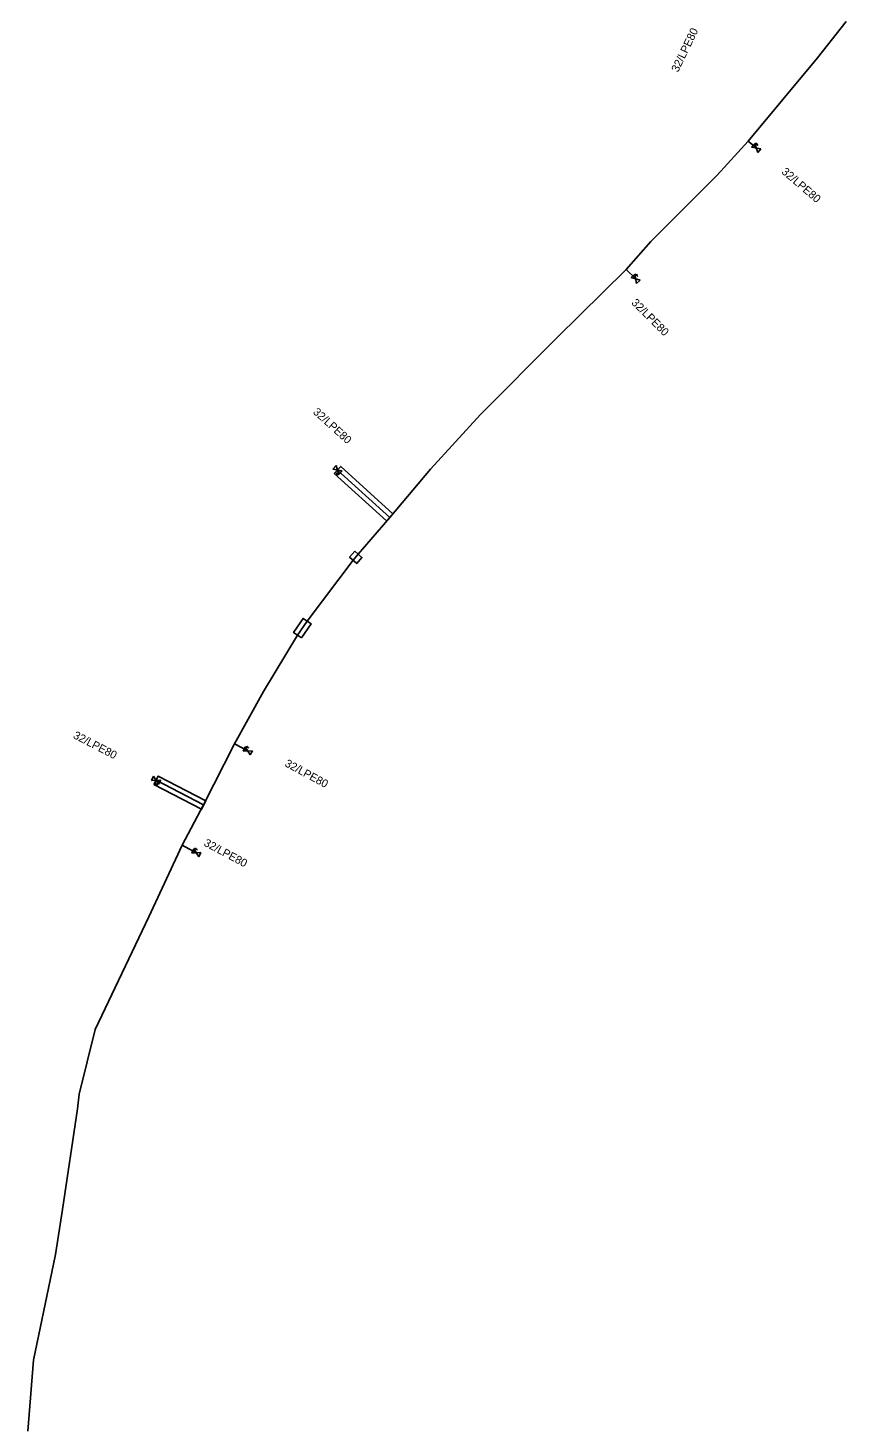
# Model space of a CAD drawing. Extents: x -787723 to -786204, y -1153846 to -1152384.
# Drawn here: x -787335.4 to -787233.1, y -1152772.9 to -1152598 of the extents above; entities that cross this region are included whole.
import ezdxf

# ---------------------------------------------------------------- set-up
doc = ezdxf.new("R2010")
doc.units = 0
for name, color, linetype in [('Vrstva 1', 7, 'Continuous'), ('Vrstva 21', 7, 'Continuous'), ('Vrstva 29', 7, 'Continuous'), ('Vrstva 31', 7, 'Continuous'), ('Vrstva 32', 7, 'Continuous')]:
    doc.layers.add(name, color=color, linetype=linetype)

# ---------------------------------------------------------------- blocks, each defined once
blk = doc.blocks.new('DEC063-SN')
at = {"layer": 'Vrstva 1'}
for p, q in [((-0.5, -0.3), (0.5, 0.3)), ((0.5, -0.3), (-0.5, 0.3)), ((-0.5, 0.3), (-0.5, -0.3)), ((0.5, 0.3), (0.5, -0.3)), ((0.126, -0.318), (0.126, -0.458)), ((0.126, -0.384), (0.206, -0.384)), ((0.206, -0.458), (0.206, -0.318)), ((0.366, -0.458), (0.366, -0.318))]:
    blk.add_line(p, q, dxfattribs=at)
for points in [[(0.246, -0.318), (0.246, -0.418), (0.252, -0.438), (0.264, -0.451), (0.281, -0.458), (0.292, -0.458), (0.309, -0.451), (0.321, -0.438), (0.326, -0.418), (0.326, -0.318)], [(0.366, -0.318), (0.418, -0.318), (0.435, -0.325), (0.441, -0.331), (0.446, -0.344), (0.446, -0.364), (0.441, -0.378), (0.435, -0.384), (0.418, -0.391), (0.366, -0.391)]]:
    blk.add_lwpolyline(points, dxfattribs=at)

msp = doc.modelspace()

# ---------------------------------------------------------------- linework, layer by layer
at = {"layer": 'Vrstva 21'}
msp.add_lwpolyline([(-787233.13, -1152597.19), (-787236.68, -1152601.75), (-787245.35, -1152612.14), (-787249.23, -1152616.39), (-787257.51, -1152624.7), (-787260.59, -1152628.17), (-787269.27, -1152636.7), (-787278.8, -1152646.28), (-787285.05, -1152653.13), (-787290.15, -1152659.16), (-787294.09, -1152663.76), (-787294.73, -1152664.5), (-787300.48, -1152672.1), (-787301.68, -1152673.87), (-787305.94, -1152680.9), (-787309.57, -1152687.43), (-787313.42, -1152695.07), (-787316.12, -1152700.09), (-787320.28, -1152709.05), (-787326.97, -1152723.12), (-787328.99, -1152731.18), (-787329.2, -1152733.02), (-787331.06, -1152745.61), (-787331.94, -1152751.23), (-787334.68, -1152764.41), (-787335.37, -1152773.31)], dxfattribs=at)
at = {"layer": 'Vrstva 29'}
for points in [[(-787297.09, -1152653.68), (-787296.29, -1152652.79), (-787289.75, -1152658.72), (-787290.55, -1152659.6)], [(-787294.54, -1152663.37), (-787293.64, -1152664.15), (-787294.28, -1152664.89), (-787295.18, -1152664.11)], [(-787301.18, -1152674.21), (-787302.18, -1152673.53), (-787300.98, -1152671.76), (-787299.98, -1152672.44)], [(-787319.64, -1152692.52), (-787319.08, -1152691.46), (-787313.14, -1152694.54), (-787313.7, -1152695.6)]]:
    msp.add_lwpolyline(points, close=True, dxfattribs=at)
at = {"layer": 'Vrstva 31'}
for points in [[(-787245.35, -1152612.14), (-787244.35, -1152613)], [(-787260.59, -1152628.17), (-787259.41, -1152629.35)], [(-787290.15, -1152659.16), (-787296.69, -1152653.24)], [(-787309.57, -1152687.43), (-787307.91, -1152688.33)], [(-787313.42, -1152695.07), (-787319.36, -1152691.99)], [(-787316.12, -1152700.09), (-787314.33, -1152701.05)]]:
    msp.add_lwpolyline(points, dxfattribs=at)

# ---------------------------------------------------------------- block references
at = {"layer": 'Vrstva 32'}
for p, rotation in [((-787244.35, -1152613), 139.54279162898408), ((-787259.41, -1152629.35), 131.0087639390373), ((-787296.69, -1152653.24), -42.15135558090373), ((-787307.91, -1152688.33), 151.85990284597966), ((-787319.36, -1152691.99), -27.407575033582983), ((-787314.33, -1152701.05), 152.65041955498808)]:
    msp.add_blockref('DEC063-SN', p, dxfattribs=dict(at, rotation=rotation))

# ---------------------------------------------------------------- texts
at = {"layer": 'Vrstva 31'}
for rotation, p in [(64.287, (-787254.12, -1152603.61)), (319.304, (-787241.27, -1152616.1)), (315, (-787260.02, -1152632.42)), (317.849, (-787299.83, -1152646.1)), (332.592, (-787329.8, -1152686.68)), (331.535, (-787303.36, -1152690.18)), (331.795, (-787313.48, -1152700.11))]:
    msp.add_text('32/LPE80', height=1, rotation=rotation, dxfattribs=at).set_placement(p)

doc.saveas('drawing.dxf')
